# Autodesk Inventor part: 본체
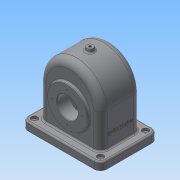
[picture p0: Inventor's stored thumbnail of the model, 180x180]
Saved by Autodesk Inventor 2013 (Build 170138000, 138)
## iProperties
Created: 2016-10
Part Number: 본체
Material: 일반
Document SubType Name: Modeling
Designer: Administrator
Density: 1 g/cm^3
Author: Administrator
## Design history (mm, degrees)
sketch "스케치1"
  geometry: L1 (-58, 0)-(58, 0); L2 (-58, 0)-(-58, 80); L3 (58, 0)-(58, 80); L4 (0, 0)-(0, 144); A1 r 58 centre (0, 80) between (58, 80) and (-58, 80); 1 further point
  constraints: 8 end point, 2 parallel, 2 point on circle, 1 centre point, 1 coincident, 1 horizontal, 1 midpoint, 1 perpendicular, 1 tangent, 1 vertical alignment
  dimensions: "d12" = 116 diameter of A1; "d13" = 80 distance of point (0, 0) A1.centre
extrude "돌출1" new body sketch "스케치1" stored distance "d15" = 77; taper "d16" = 0 deg
sketch "스케치3"
  geometry: L1 (58, 80)-(58, 0) reference; L2 (58, 0)-(-58, 0) reference; L3 (58, 0)-(-58, 0) reference; L4 (-58, 0)-(-58, 80) reference; L5 (58, 80)-(58, 0) reference; L6 (52, 80)-(52, 0); L7 (-52, 80)-(-52, 0); A1 r 58 centre (0, 80) between (58, 80) and (-58, 80) reference; A2 r 58 centre (0, 80) between (58, 80) and (-58, 80) reference; A3 r 52 centre (0, 80) between (52, 80) and (-52, 80); 1 further point
  constraints: 4 end point, 2 parallel, 2 point on circle, 2 point on line, 2 tangent, 1 centre point
  dimensions: "d17" = 6 radial gap between concentric circles of A1 A3
extrude "돌출2" cut sketch "스케치3" stored distance "d19" = 67; taper "d20" = 0 deg
sketch "스케치5"
  geometry: L1 (-58, 0)-(58, 0) reference; C1 r 37.5 at (0, 65); A1 r 58 centre (0, 80) between (58, 80) and (-58, 80) reference; 1 further point
  constraints: 1 centre point, 1 vertical alignment
  dimensions: "d23" = 75 diameter of C1; "d25" = 65 distance from line of L1 C1.centre
extrude "돌출3" join sketch "스케치5" distance "d26" = 5; taper "d27" = 0 deg
node "작업 평면1"
sketch "스케치6"
  geometry: L1 (52, -65)-(-52, -65) reference; C1 r 28 at (0, 0); 2 further points
  constraints: 1 centre point, 1 midpoint, 1 vertical alignment
  dimensions: "d29" = 65 distance from line of L1 C1.centre; "d30" = 56 diameter of C1
extrude "돌출4" join sketch "스케치6" stored distance "d31" = 5; taper "d32" = 40 deg
sketch "스케치7"
  geometry: C1 r 37.5 at (0, 0) reference; C2 r 20 at (0, 0); 1 further point
  constraints: 1 centre point, 1 coincident
  dimensions: "d33" = 40 diameter of C2
extrude "돌출5" cut sketch "스케치7" distance "d34" = 24; taper "d35" = 0 deg
sketch "스케치8"
  geometry: L1 (58, 0)-(-58, 0) reference; C1 r 31 at (0, -65); 2 further points
  constraints: 1 centre point, 1 midpoint, 1 vertical alignment
  dimensions: "d36" = 62 diameter of C1; "d37" = 65 distance from line of L1 C1.centre
extrude "돌출6" join sketch "스케치8" distance "d38" = 10; taper "d39" = 0 deg
sketch "스케치9"
  geometry: C1 r 31 at (0, 0) reference; C2 r 20 at (0, 0); 1 further point
  constraints: 1 centre point, 1 coincident
  dimensions: "d40" = 40 diameter of C2
extrude "돌출7" cut sketch "스케치9" distance "d41" = 15; taper "d42" = 0 deg
sketch "스케치10"
  geometry: L1 (0, 0)-(0, -26); C1 r 31 at (0, 0) reference; 2 further points
  constraints: 2 end point, 1 coincident, 1 vertical
  dimensions: "d43" = 26 distance of L1.start L1.end
hole "구멍1" sketch "스케치10" at (0, -26) diameter "d44" = 2.459; stored, may be unused: countersink angle "d48" = 90 deg, drill point angle "d50" = 118 deg; dims "d45" = 6, "d46" = 4, "d47" = 2, "d49" = 8
chamfer "모따기1" distance "d54" = 1; stored, may be unused: second distance "d55" = 2, angle "d56" = 45 deg
node "작업 평면3"
sketch "스케치12"
  geometry: L1 (-110, -72)-(-6, -72) reference; C1 r 6 at (-58, -38.5); 1 further point
  constraints: 1 centre point, 1 coincident
  dimensions: "d63" = 12 diameter of C1; "d64" = 33.5 distance from line of C1.centre L1
extrude "돌출8" join sketch "스케치12" stored distance "d65" = 15; taper "d66" = 10 deg
fillet "모깎기3" dims "d67" = 3
fillet "모깎기1" dims "d57" = 8
fillet "모깎기2" dims "d58" = 13
hole "구멍2" diameter "d70" = 4.459; stored, may be unused: countersink angle "d74" = 90 deg, drill point angle "d76" = 118 deg; dims "d68" = 10, "d69" = 10, "d71" = 99, "d72" = 4, "d73" = 2, "d75" = 8
fillet "모깎기4" dims "d77" = 3
sketch "스케치13"
  geometry: L1 (0, 0)-(90, 0) reference; L2 (-13, -13)-(-13, -64) reference; L3 (90, -77)-(0, -77) reference; L4 (103, -64)-(103, -13) reference; L5 (120, -93.5)-(-30, -93.5); L6 (-30, -93.5)-(-30, 16.5); L7 (-30, 16.5)-(120, 16.5); L8 (120, 16.5)-(120, -93.5); L9 (120, -93.5)-(-30, 16.5); L10 (-30, -93.5)-(120, 16.5); A1 r 13 centre (90, -13) between (103, -13) and (90, 0) reference; A2 r 13 centre (0, -13) between (0, 0) and (-13, -13) reference; A3 r 13 centre (0, -64) between (-13, -64) and (0, -77) reference; A4 r 13 centre (90, -64) between (90, -77) and (103, -64) reference; 1 further point
  constraints: 12 end point, 2 midpoint, 2 parallel, 1 horizontal, 1 perpendicular
  dimensions: "d78" = 110 distance between parallel lines of L5 L7; "d80" = 150 distance of L6.end L7.end
extrude "돌출9" join sketch "스케치13" distance "d81" = 15; taper "d82" = 0 deg
fillet "모깎기5" dims "d83" = 12
fillet "모깎기6" dims "d84" = 3
hole "구멍3" diameter "d87" = 5; stored, may be unused: countersink angle "d91" = 82 deg, drill point angle "d93" = 118 deg; dims "d85" = 10, "d86" = 10, "d88" = 99, "d89" = 12, "d90" = 5, "d92" = 8
fillet "모깎기7" dims "d94" = 3
sketch "스케치14"
  geometry: L1 (80, -17.5)-(80, 68.5) reference; L2 (0, -13)-(62, -13) reference; 2 further points
  constraints: 1 other
  dimensions: "d95" = 40 distance from line of L1 point (40, 25.5); "d96" = 38.5 distance from line of point (40, 25.5) L2
feature "엠보싱1" sketch "스케치14" dims "d17" = 6, "d97" = 0.5, "d98" = 0
sketch "스케치15"
  geometry: L1 (0, 0)-(0, 29); C1 r 21 at (0, 0) reference; 2 further points
  constraints: 2 end point, 1 coincident, 1 vertical
  dimensions: "d99" = 29 distance of L1.start L1.end
hole "구멍4" sketch "스케치15" at (0, 29) diameter "d100" = 2.459; stored, may be unused: countersink angle "d104" = 82 deg, drill point angle "d106" = 118 deg; dims "d101" = 6, "d102" = 12, "d103" = 5, "d105" = 8
node "솔리드1"
pattern_circular "원형 패턴1" dims angle "d52" = 360 deg
mirror "대칭2"
mirror "대칭3"
pattern_circular "원형 패턴2" dims angle "d108" = 360 deg
node "투영된 루프1"
other parameters: "d28" = -24, "d62" = -144
